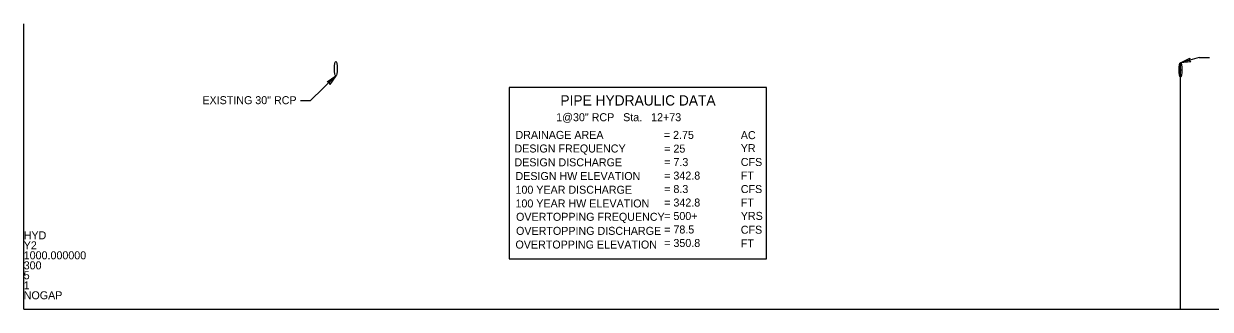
# Model space of a CAD drawing. Extents: x 2044939 to 2046718, y 752715 to 754848.
# Drawn here: x 2044939 to 2045977, y 752715 to 752965 of the extents above; entities that cross this region are included whole.
import ezdxf

# ---------------------------------------------------------------- set-up
doc = ezdxf.new("R2010")
doc.units = 0
for name, color, linetype in [('Exist Profile Cell', 7, 'Continuous'), ('Prop Grid Mask', 7, 'Continuous'), ('Prop PFL Cross Pipe Text CELL', 7, 'Continuous'), ('Prop PFL Pipe Hydraulic Data CELL', 7, 'Continuous'), ('Prop Terminator CELL', 7, 'Continuous'), ('Scratch_Level_2', 7, 'Continuous')]:
    doc.layers.add(name, color=color, linetype=linetype)

msp = doc.modelspace()

# ---------------------------------------------------------------- linework, layer by layer
at = {"layer": 'Exist Profile Cell'}
for q in [(2044939.4, 752965.2), (2046718.3, 752715.2), (2044939.4, 752715.2)]:
    msp.add_line((2044939.4, 752715.2), q, dxfattribs=at)
at = {"layer": 'Prop Grid Mask'}
msp.add_lwpolyline([(2045364.1, 752759.3), (2045589.1, 752759.3), (2045589.1, 752909.3), (2045364.1, 752909.3)], close=True, dxfattribs=at)
at = {"layer": 'Prop PFL Cross Pipe Text CELL'}
for p, q in [((2045967.7, 752935.8), (2045951.4, 752931)), ((2045967.7, 752935.8), (2045976.7, 752935.8)), ((2045190.4, 752897.9), (2045212.4, 752919.6)), ((2045181.4, 752897.9), (2045190.4, 752897.9))]:
    msp.add_line(p, q, dxfattribs=at)
for centre in [(2045212.4, 752925.9), (2045951.4, 752924.8)]:
    msp.add_ellipse(centre, major_axis=(0, 6.25), ratio=0.2, dxfattribs=at)
at = {"layer": 'Prop Terminator CELL'}
for points in [[(2045960.5, 752932), (2045951.4, 752931), (2045959.6, 752935.1), (2045959, 752933.2)], [(2045204.9, 752914.4), (2045212.4, 752919.6), (2045207.1, 752912.1), (2045206.8, 752914.1)]]:
    msp.add_lwpolyline(points, close=True, dxfattribs=at)
at = {"layer": 'Scratch_Level_2'}
for p, q in [((2045951.4, 752918.5), (2045951.4, 752931)), ((2045951.4, 752924.8), (2045950.2, 752924.8)), ((2045951.4, 752924.8), (2045952.7, 752924.8)), ((2045951.4, 752715.2), (2045951.4, 752918.5)), ((2044939.4, 752715.2), (2045951.4, 752715.2))]:
    msp.add_line(p, q, dxfattribs=at)

# ---------------------------------------------------------------- texts
at = {"layer": 'Exist Profile Cell'}
for s, p in [('HYD', (2044939.4, 752776.5)), ('Y2', (2044939.4, 752767.7)), ('1000.000000', (2044939.4, 752759)), ('300', (2044939.4, 752750.2)), ('5', (2044939.4, 752741.5)), ('1', (2044939.4, 752732.7)), ('NOGAP', (2044939.4, 752724))]:
    msp.add_text(s, height=7, dxfattribs=at).set_placement(p)
at = {"layer": 'Prop PFL Cross Pipe Text CELL'}
msp.add_text('EXISTING 30" RCP', height=7, dxfattribs=at).set_placement((2045095.7, 752894.8))
at = {"layer": 'Prop PFL Pipe Hydraulic Data CELL'}
for s, height, p in [('PIPE HYDRAULIC DATA', 9, (2045408.9, 752893.6)), (' 1@30" RCP   Sta.   12+73   ', 7, (2045402.6, 752879.9)), ('DRAINAGE AREA', 7, (2045369.6, 752864.4)), ('= 2.75   ', 7, (2045499.4, 752864.4)), ('AC', 7, (2045566.7, 752864.2)), ('DESIGN FREQUENCY', 7, (2045368.7, 752852.5)), ('= 25 ', 7, (2045499.7, 752852.4)), ('YR', 7, (2045566.7, 752852.8)), ('DESIGN DISCHARGE', 7, (2045368.7, 752840.4)), ('= 7.3     ', 7, (2045499.7, 752840.6)), ('CFS', 7, (2045566.7, 752840.7)), ('DESIGN HW ELEVATION', 7, (2045369.6, 752828.4)), ('= 342.8   ', 7, (2045499.7, 752828.8)), ('FT', 7, (2045566.7, 752828.8)), ('100 YEAR DISCHARGE', 7, (2045369.6, 752816.4)), ('= 8.3     ', 7, (2045499.7, 752817)), ('CFS', 7, (2045566.7, 752817)), ('= 342.8   ', 7, (2045499.7, 752805.2)), ('100 YEAR HW ELEVATION', 7, (2045369.6, 752804.4)), ('FT', 7, (2045566.7, 752805.2)), ('OVERTOPPING FREQUENCY', 7, (2045370.1, 752792.7)), ('= 500+', 7, (2045499.7, 752793.4)), ('YRS', 7, (2045566.7, 752793.5)), ('OVERTOPPING DISCHARGE', 7, (2045370.1, 752780.4)), ('= 78.5    ', 7, (2045499.7, 752781.6)), ('CFS', 7, (2045566.7, 752781.4)), ('OVERTOPPING ELEVATION', 7, (2045369.6, 752768.4)), ('= 350.8   ', 7, (2045499.7, 752769.8)), ('FT', 7, (2045566.7, 752769.4))]:
    msp.add_text(s, height=height, dxfattribs=at).set_placement(p)

doc.saveas('drawing.dxf')
